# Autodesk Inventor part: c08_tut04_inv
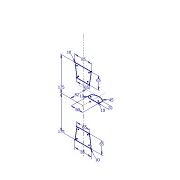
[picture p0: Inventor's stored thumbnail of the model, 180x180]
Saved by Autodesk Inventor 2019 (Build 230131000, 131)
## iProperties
Created: 2015-03
Part Number: c08_tut04_inv
Material: Generic
Document SubType Name: Modeling
Designer: Sandeep
Density: 1 g/cm^3
Appearance: Blue - Glazing
Mass: 996.637 g
Surface Area: 881.078 cm^2
Volume: 996.637 cm^3
Author: Sandeep
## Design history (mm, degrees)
sketch "Sketch1"
  geometry: L1 (-20, 50.541)-(20, 50.541); L2 (30, 60.541)-(30, 70.541); L3 (-30, 60.541)-(-30, 70.541); L4 (0, -9.695)-(0, 120.745); L5 (0, 82)-(-105.666, 82); A1 r 45 centre (0, 37) between (30, 70.541) and (-30, 70.541); A2 r 10 centre (-20, 60.541) between (-30, 60.541) and (-20, 50.541); A3 r 10 centre (20, 60.541) between (20, 50.541) and (30, 60.541); 2 further points
  constraints: 10 end point, 7 point on circle, 5 point on line, 4 tangent, 3 centre point, 2 horizontal, 2 vertical, 1 perpendicular, 1 other
  dimensions: "d0" = 60 distance between parallel lines of L2 L3; "d2" = 20 distance of point (30, 50.541) L2.end; "d3" = 45 radius of A1; "d4" = 10 radius of A2; "d5" = 10 radius of A3; "d22" = 82 distance from line of point (0, 0) L5
sketch "Sketch2"
  geometry: L1 (30.844, 175)-(-30.844, 175); L2 (-40.728, 163.479)-(-33.805, 118.479); L3 (-23.921, 110)-(23.921, 110); L4 (33.805, 118.479)-(40.728, 163.479); L5 (0, 0)-(0, 325.346); A1 r 10 centre (30.844, 165) between (40.728, 163.479) and (30.844, 175); A2 r 10 centre (-30.844, 165) between (-30.844, 175) and (-40.728, 163.479); A3 r 10 centre (-23.921, 120) between (-33.805, 118.479) and (-23.921, 110); A4 r 10 centre (23.921, 120) between (23.921, 110) and (33.805, 118.479); 4 further points
  constraints: 10 end point, 8 point on circle, 8 point on line, 8 tangent, 4 centre point, 3 equal radius, 1 horizontal, 1 parallel, 1 vertical, 1 other
  dimensions: "d6" = 65 distance of point (-32.5, 110) point (32.5, 110); "d7" = 65 distance between parallel lines of L1 L3; "d8" = 85 distance of point (42.5, 175) point (-42.5, 175); "d9" = 175 distance from line of L5.start L1; "d10" = 10 radius of A1
sketch "Sketch5"
  geometry: L1 (23.921, -110)-(-23.921, -110); L2 (-33.805, -118.479)-(-40.728, -163.479); L3 (-30.844, -175)-(30.844, -175); L4 (40.728, -163.479)-(33.805, -118.479); L5 (0, 0)-(0, -235.653); A1 r 10 centre (-30.844, -165) between (-40.728, -163.479) and (-30.844, -175); A2 r 10 centre (30.844, -165) between (30.844, -175) and (40.728, -163.479); A3 r 10 centre (23.921, -120) between (33.805, -118.479) and (23.921, -110); A4 r 10 centre (-23.921, -120) between (-23.921, -110) and (-33.805, -118.479); 4 further points
  constraints: 10 end point, 8 point on circle, 8 point on line, 8 tangent, 4 centre point, 3 equal radius, 1 horizontal, 1 parallel, 1 vertical, 1 other
  dimensions: "d11" = 65 distance of point (32.5, -110) point (-32.5, -110); "d12" = 85 distance of point (-42.5, -175) point (42.5, -175); "d13" = 65 distance between parallel lines of L1 L3; "d14" = 175 distance from line of L5.start L3; "d15" = 10 radius of A1
body "Solid1"
